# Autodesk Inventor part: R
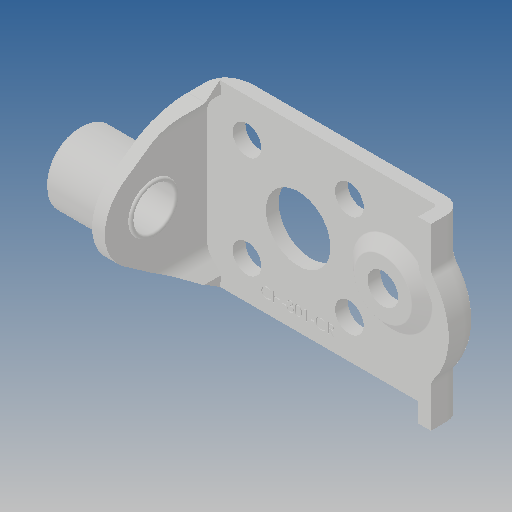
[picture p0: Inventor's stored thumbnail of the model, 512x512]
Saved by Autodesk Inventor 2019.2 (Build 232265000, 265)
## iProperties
Created: 2012-09
Part Number: R
Material: Ogólny
Document SubType Name: Modeling
Designer: CADENGINEERING4
Density: 1 g/cm^3
Appearance: Domyślna
Author: CADENGINEERING4
Revision Number: ÈÎºÎ
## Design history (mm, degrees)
feature "ÇÐ³ý-À­Éì4"
node "Bryła1"
